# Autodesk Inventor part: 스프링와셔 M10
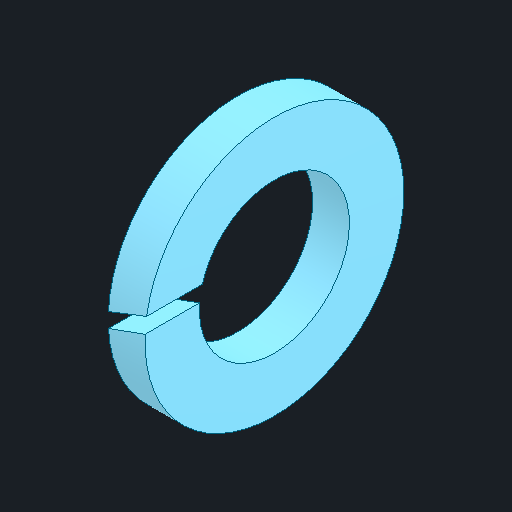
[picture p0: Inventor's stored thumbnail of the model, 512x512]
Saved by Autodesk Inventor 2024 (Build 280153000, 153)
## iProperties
Created: 2025-02
Part Number: 스프링와셔 M10
Material: 강철, 연강
Description: 스프링 잠금 와셔
Document SubType Name: Modeling
Designer: kh_501
Density: 7.85 g/cm^3
Appearance: 기본값
Author: jhkim
Sending System: Autodesk Inventor 2025
Preprocessor: ST-DEVELOPER v20
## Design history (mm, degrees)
feature "Solid1"
node "솔리드1"
